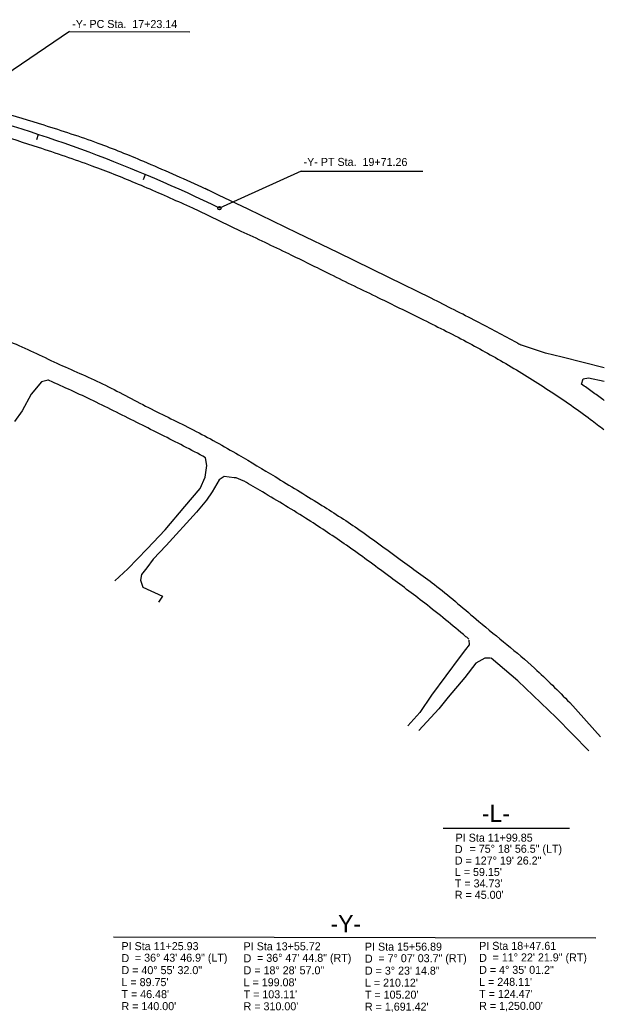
# Model space of a CAD drawing. Extents: x 757145 to 758829, y 592169 to 594973.
# Drawn here: x 758280 to 758791, y 593970 to 594838 of the extents above; entities that cross this region are included whole.
import ezdxf

# ---------------------------------------------------------------- set-up
doc = ezdxf.new("R2010")
doc.units = 0
for name, color, linetype in [('Default', 7, 'Continuous'), ('Exist Horizontal Alignment', 7, 'Continuous'), ('Exist Horizontal Alignment Curve and Spiral Data', 7, 'Continuous'), ('Exist Horizontal Alignment Station Label', 7, 'Continuous'), ('Exist Horizontal Alignment Tick Small', 7, 'Continuous'), ('Prop Roadway Bridge', 7, 'Continuous'), ('Scratch_Level_2', 7, 'Continuous')]:
    doc.layers.add(name, color=color, linetype=linetype)

msp = doc.modelspace()

# ---------------------------------------------------------------- linework, layer by layer
at = {"layer": 'Default'}
for p, q in [((758444.56, 594688.85), (758438.83, 594691.7)), ((758453.63, 594684.64), (758441.73, 594690.41)), ((758431.33, 594673.19), (758435.79, 594671.21)), ((758435.79, 594671.21), (758473.14, 594653.2)), ((758739.59, 594546.27), (758717.6, 594553.57)), ((758754.12, 594542.75), (758739.59, 594546.27)), ((758790.84, 594533.53), (758754.12, 594542.75)), ((758298.6, 594521.15), (758289.61, 594510.42)), ((758304.36, 594522.77), (758298.6, 594521.15)), ((758771.04, 594519.24), (758772.37, 594523.93)), ((758772.37, 594523.93), (758777.03, 594524.63)), ((758777.03, 594524.63), (758790.81, 594521.88)), ((758289.61, 594510.42), (758281.66, 594495.95)), ((758281.66, 594495.95), (758275.1, 594486.51)), ((758443.43, 594447.93), (758442.25, 594454.9)), ((758441.8, 594437.85), (758443.43, 594447.93)), ((758437.33, 594427.91), (758441.8, 594437.81)), ((758441.8, 594437.81), (758441.8, 594437.85)), ((758454.22, 594435.44), (758448, 594424.95)), ((758458.38, 594438.35), (758454.22, 594435.44)), ((758467.15, 594437.21), (758458.38, 594438.35)), ((758469.07, 594437.29), (758467.15, 594437.21)), ((758475.17, 594434.6), (758469.07, 594437.29)), ((758475.85, 594434.21), (758475.17, 594434.6)), ((758424.18, 594412.09), (758437.33, 594427.91)), ((758448, 594424.95), (758442.88, 594417.71)), ((758442.88, 594417.71), (758434.3, 594407.3)), ((758406.92, 594391.78), (758424.18, 594412.09)), ((758434.3, 594407.3), (758407.82, 594378.1)), ((758391.15, 594375.17), (758406.92, 594391.78)), ((758374.27, 594357.73), (758391.15, 594375.17)), ((758407.82, 594378.1), (758396.29, 594366.17)), ((758396.29, 594366.17), (758390.7, 594358.54)), ((758362.87, 594347.09), (758374.27, 594357.73)), ((758390.7, 594358.54), (758386.14, 594352.76)), ((758386.14, 594352.76), (758385.37, 594347.72)), ((758385.37, 594347.72), (758387.39, 594341.7)), ((758387.39, 594341.7), (758404.47, 594333.72)), ((758404.47, 594333.72), (758401.01, 594328.51)), ((758672.39, 594295.14), (758672.87, 594291.17)), ((758669.52, 594287.03), (758664.78, 594280.86)), ((758672.87, 594291.17), (758669.52, 594287.03)), ((758664.78, 594280.86), (758639.71, 594247.11)), ((758686.45, 594279.5), (758678.72, 594275.24)), ((758691.43, 594279.42), (758686.45, 594279.5)), ((758715.39, 594259.56), (758691.93, 594279.55)), ((758678.72, 594275.24), (758669.06, 594262.45)), ((758669.06, 594262.45), (758654.51, 594245.29)), ((758639.71, 594247.11), (758629.6, 594232.01)), ((758654.51, 594245.29), (758646.16, 594235.17)), ((758646.16, 594235.17), (758628.88, 594216.21)), ((758760.77, 594240.66), (758787.69, 594210.79)), ((758629.6, 594232.01), (758619.18, 594220.26))]:
    msp.add_line(p, q, dxfattribs=at)
for points in [[(758639.66, 594594.31), (758602.56, 594612.56), (758557.78, 594634.46), (758522.7, 594651.31), (758479.56, 594672.39), (758453.63, 594684.64)], [(758777.45, 594198.34), (758748.87, 594227.71), (758715.39, 594259.56)]]:
    msp.add_lwpolyline(points, dxfattribs=at)
for points in [[(758438.83, 594691.7), (758388.12, 594713.96), (758348.23, 594729.88), (758301, 594745.68), (758262.18, 594757.5), (758218.1, 594769.85), (758179.06, 594780.3), (758137.21, 594790.72), (758099.24, 594799.92), (758057.04, 594808.54), (758015.02, 594816.54), (757976.3, 594823.06), (757929.26, 594827.65), (757885.54, 594826.92), (757867.17, 594824.62)], [(757759.9, 594765.22), (757801.95, 594785.45), (757843.04, 594799.54), (757887.75, 594807.17), (757928.75, 594808.19), (757973.34, 594803.82), (758011.28, 594797.5), (758054.09, 594789.21), (758096.75, 594780.39), (758132.99, 594771.58), (758175.84, 594760.81), (758214.12, 594750.43), (758258.48, 594738.29), (758295.65, 594726.54), (758342.77, 594710.33), (758380.69, 594695.36), (758421.02, 594677.79), (758431.33, 594673.19)], [(758473.14, 594653.2), (758514.62, 594633.49), (758551.09, 594615.5), (758593.44, 594594.83)], [(757891.94, 594602.51), (757928.7, 594613.12), (757974.81, 594621.08), (758013.38, 594621.87), (758059.79, 594614.97), (758103.42, 594606.71), (758144.86, 594596.26), (758186.7, 594584.49), (758228.79, 594570.5), (758271.22, 594556.18), (758311.98, 594537.66), (758352.07, 594519.49), (758392.24, 594498.74), (758431.47, 594479.21), (758471.03, 594457.32), (758502.93, 594438.31), (758541.94, 594414.39), (758575.01, 594392.91), (758612.38, 594365.9), (758644.48, 594342.28), (758681.18, 594311.67), (758729.99, 594270.62), (758760.77, 594240.66)], [(758593.44, 594594.83), (758630.37, 594576.77), (758670.48, 594556.28), (758707.04, 594535.84), (758725.92, 594524.43), (758744.51, 594512.53), (758779.01, 594488.39), (758790.7, 594479.52)], [(758717.88, 594553.42), (758714.65, 594555.23), (758679.57, 594573.95), (758639.66, 594594.31)], [(758442.25, 594454.9), (758422.86, 594465.07), (758384.49, 594484.48), (758344.04, 594504.59), (758305.43, 594522.3), (758304.24, 594522.82)], [(758790.77, 594504.93), (758789.61, 594505.79), (758780.36, 594512.56), (758771.04, 594519.24)], [(758672.61, 594296.02), (758669.94, 594298.29), (758633.9, 594327.56), (758602.11, 594351.6), (758565.49, 594378.2), (758532.02, 594400.45), (758491.85, 594424.91), (758475.85, 594434.21)]]:
    msp.add_spline(points, degree=3, dxfattribs=at)
at = {"layer": 'Exist Horizontal Alignment'}
msp.add_arc((757905.22, 593550.23), 1250, 63.94354, 75.31629, dxfattribs=at)
at = {"layer": 'Exist Horizontal Alignment Curve and Spiral Data'}
msp.add_line((758361.68, 594035.63), (758783.47, 594034.86), dxfattribs=at)
at = {"layer": 'Exist Horizontal Alignment Station Label'}
for p, q in [((758323.31, 594827.62), (758222.08, 594759.4)), ((758323.31, 594827.62), (758428.52, 594827.43)), ((758525.67, 594705.62), (758454.29, 594673.18)), ((758525.67, 594705.62), (758632.27, 594705.43))]:
    msp.add_line(p, q, dxfattribs=at)
msp.add_circle((758454.29, 594673.18), 1.5, dxfattribs=at)
at = {"layer": 'Exist Horizontal Alignment Tick Small'}
for p, q in [((758295.78, 594737.65), (758294.22, 594732.9)), ((758389.42, 594702.64), (758387.48, 594698.03))]:
    msp.add_line(p, q, dxfattribs=at)
at = {"layer": 'Prop Roadway Bridge'}
msp.add_line((758650, 594130.64), (758760.51, 594130.61), dxfattribs=at)

# ---------------------------------------------------------------- texts
at = {"layer": 'Exist Horizontal Alignment Curve and Spiral Data'}
msp.add_text('-Y-', height=15, rotation=359.89587, dxfattribs=at).set_placement((758551.48, 594039.75))
for s, p in [('PI Sta 11+25.93', (758368.64, 594024.04)), ('PI Sta 13+55.72', (758475.47, 594023.9)), ('PI Sta 15+56.89', (758581.59, 594023.58)), ('PI Sta 18+47.61', (758681.5, 594024.29)), ('D', (758368.64, 594013.54)), ('= 36%%d 43\' 46.9" (LT)', (758380.41, 594013.93)), ('D', (758475.47, 594013.4)), ('= 36%%d 47\' 44.8" (RT)', (758487.24, 594013.79)), ('D', (758581.59, 594013.08)), ('= 7%%d 07\' 03.7" (RT)', (758593.36, 594013.47)), ('D', (758681.5, 594013.79)), ('= 11%%d 22\' 21.9" (RT)', (758693.27, 594014.18)), ('D = 40%%d 55\' 32.0"', (758368.64, 594003.04)), ('D = 18%%d 28\' 57.0"', (758475.47, 594002.9)), ('D = 3%%d 23\' 14.8"', (758581.59, 594002.58)), ('D = 4%%d 35\' 01.2"', (758681.5, 594003.29)), ("L = 89.75'", (758368.64, 593992.54)), ("L = 199.08'", (758475.47, 593992.4)), ("L = 210.12'", (758581.59, 593992.08)), ("L = 248.11'", (758681.5, 593992.79)), ("T = 46.48'", (758368.64, 593982.04)), ("T = 103.11'", (758475.47, 593981.9)), ("T = 105.20'", (758581.59, 593981.58)), ("T = 124.47'", (758681.5, 593982.29)), ("R = 140.00'", (758368.64, 593971.54)), ("R = 310.00'", (758475.47, 593971.4)), ("R = 1,691.42'", (758581.59, 593971.08)), ("R = 1,250.00'", (758681.5, 593971.79))]:
    msp.add_text(s, height=7, dxfattribs=at).set_placement(p)
at = {"layer": 'Exist Horizontal Alignment Station Label'}
for s, p in [('-Y- PC Sta.  17+23.14', (758325.53, 594830.89)), ('-Y- PT Sta.  19+71.26', (758527.94, 594710.22))]:
    msp.add_text(s, height=7, rotation=359.89587, dxfattribs=at).set_placement(p)
at = {"layer": 'Prop Roadway Bridge'}
msp.add_text('-L-', height=15, rotation=359.89587, dxfattribs=at).set_placement((758683.88, 594136.27))
at = {"layer": 'Scratch_Level_2'}
for s, p in [('PI Sta 11+99.85', (758660.92, 594118.92)), ('D', (758660.25, 594108.92)), ('= 75%%d 18\' 56.5" (LT)', (758673.1, 594109.22)), ('D = 127%%d 19\' 26.2"', (758660.25, 594098.92)), ("L = 59.15'", (758660.25, 594088.92)), ("T = 34.73'", (758660.25, 594078.92)), ("R = 45.00'", (758660.25, 594068.92))]:
    msp.add_text(s, height=7, dxfattribs=at).set_placement(p)

doc.saveas('drawing.dxf')
